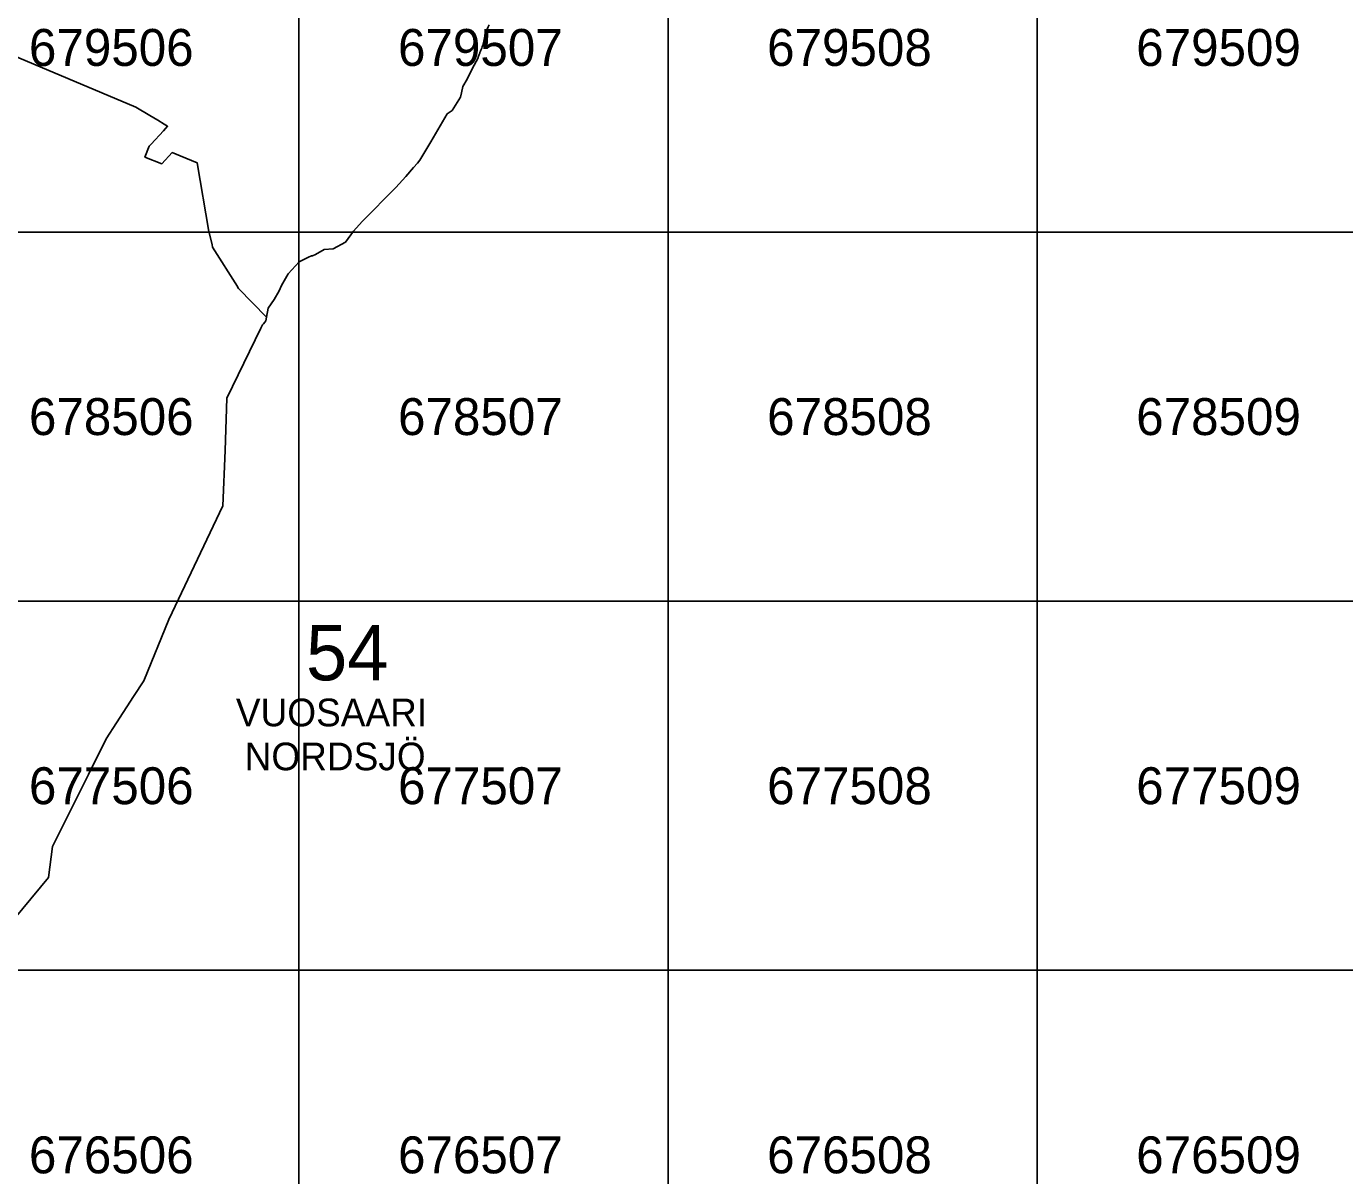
# Model space of a CAD drawing. Extents: x 25485000 to 25520000, y 6656775 to 6690000.
# Drawn here: x 25506262 to 25509833, y 6676444 to 6679557 of the extents above; entities that cross this region are included whole.
import ezdxf

# ---------------------------------------------------------------- set-up
doc = ezdxf.new("R2010")
doc.units = 0
doc.layers.add('Level 63', color=7, linetype='Continuous')

msp = doc.modelspace()

# ---------------------------------------------------------------- linework, layer by layer
at = {"layer": 'Level 63'}
for points in [[(25506000, 6679000), (25507000, 6679000), (25507000, 6680000), (25506000, 6680000)], [(25507000, 6679000), (25508000, 6679000), (25508000, 6680000), (25507000, 6680000)], [(25508000, 6679000), (25509000, 6679000), (25509000, 6680000), (25508000, 6680000)], [(25509000, 6679000), (25510000, 6679000), (25510000, 6680000), (25509000, 6680000)], [(25506000, 6678000), (25507000, 6678000), (25507000, 6679000), (25506000, 6679000)], [(25507000, 6678000), (25508000, 6678000), (25508000, 6679000), (25507000, 6679000)], [(25508000, 6678000), (25509000, 6678000), (25509000, 6679000), (25508000, 6679000)], [(25509000, 6678000), (25510000, 6678000), (25510000, 6679000), (25509000, 6679000)], [(25506000, 6677000), (25507000, 6677000), (25507000, 6678000), (25506000, 6678000)], [(25507000, 6677000), (25508000, 6677000), (25508000, 6678000), (25507000, 6678000)], [(25508000, 6677000), (25509000, 6677000), (25509000, 6678000), (25508000, 6678000)], [(25509000, 6677000), (25510000, 6677000), (25510000, 6678000), (25509000, 6678000)], [(25506000, 6676000), (25507000, 6676000), (25507000, 6677000), (25506000, 6677000)], [(25507000, 6676000), (25508000, 6676000), (25508000, 6677000), (25507000, 6677000)], [(25508000, 6676000), (25509000, 6676000), (25509000, 6677000), (25508000, 6677000)], [(25509000, 6676000), (25510000, 6676000), (25510000, 6677000), (25509000, 6677000)]]:
    msp.add_lwpolyline(points, close=True, dxfattribs=at)
for points in [[(25507515.5, 6679561.1), (25507513.1, 6679555.6), (25507508.1, 6679545.7), (25507506.4, 6679541.6), (25507505.4, 6679538.3), (25507503.5, 6679531), (25507500.8, 6679517.2), (25507498.2, 6679506.2), (25507496.6, 6679501.6), (25507495.2, 6679497.8), (25507492.9, 6679492.9), (25507491.6, 6679489.8), (25507490.3, 6679486.4), (25507489.8, 6679484.6), (25507488.5, 6679480.9), (25507486.9, 6679476), (25507484.7, 6679469.7), (25507470, 6679444.1), (25507455.8, 6679413.7), (25507443.7, 6679394.4), (25507440.3, 6679377.4), (25507437.6, 6679365), (25507415.1, 6679329), (25507401.8, 6679320), (25507357.5, 6679244.3), (25507327.2, 6679194.8), (25507321.6, 6679186.6), (25507310.2, 6679175), (25507289.3, 6679150.8), (25507262.5, 6679120.9), (25507171.6, 6679028.7), (25507147.8, 6679002.3), (25507126.6, 6678972.8), (25507092.5, 6678954.8), (25507068.5, 6678952.8), (25507045, 6678939.4), (25507036.5, 6678935.9), (25507034.3, 6678935.3), (25507025.8, 6678931.9), (25507000.8, 6678919.3), (25506971.1, 6678886.9), (25506953.1, 6678855.5), (25506946.7, 6678841), (25506932.5, 6678817.5), (25506916.2, 6678793.6), (25506912, 6678769.7), (25506836.4, 6678847.3), (25506834.8, 6678849.8), (25506833.5, 6678852.1), (25506766, 6678959.2), (25506764.6, 6678966.4), (25506755.9, 6679001.4), (25506724, 6679187.7), (25506677.9, 6679206.3), (25506656.1, 6679215.1), (25506628.2, 6679184.8), (25506582.7, 6679203.1), (25506594.6, 6679232.4), (25506599.5, 6679237.8), (25506633.2, 6679274.4), (25506644.2, 6679286.4), (25506634.8, 6679292.3), (25506617.4, 6679302.7), (25506595.6, 6679315.7), (25506558.1, 6679338.5), (25506096.7, 6679532.6)], [(25507515.5, 6679561.1), (25507513.1, 6679555.6), (25507508.1, 6679545.7), (25507506.4, 6679541.6), (25507505.4, 6679538.3), (25507503.5, 6679531), (25507500.8, 6679517.2), (25507498.2, 6679506.2), (25507496.6, 6679501.6), (25507495.2, 6679497.8), (25507492.9, 6679492.9), (25507491.6, 6679489.8), (25507490.3, 6679486.4), (25507489.8, 6679484.6), (25507488.5, 6679480.9), (25507486.9, 6679476), (25507484.7, 6679469.7), (25507470, 6679444.1), (25507455.8, 6679413.7), (25507443.7, 6679394.4), (25507440.3, 6679377.4), (25507437.6, 6679365), (25507415.1, 6679329), (25507401.8, 6679320), (25507357.5, 6679244.3), (25507327.2, 6679194.8), (25507321.6, 6679186.6), (25507310.2, 6679175), (25507289.3, 6679150.8), (25507262.5, 6679120.9), (25507171.6, 6679028.7), (25507147.8, 6679002.3), (25507126.6, 6678972.8), (25507092.5, 6678954.8), (25507068.5, 6678952.8), (25507045, 6678939.4), (25507036.5, 6678935.9), (25507034.3, 6678935.3), (25507025.8, 6678931.9), (25507000.8, 6678919.3), (25506971.1, 6678886.9), (25506953.1, 6678855.5), (25506946.7, 6678841), (25506932.5, 6678817.5), (25506916.2, 6678793.6), (25506910.1, 6678759.2), (25506908, 6678755.6), (25506903.8, 6678751.5), (25506901.5, 6678748.7), (25506897.1, 6678739.9), (25506804.8, 6678550), (25506799.9, 6678408.5), (25506794.2, 6678258.1), (25506647.7, 6677950.1), (25506579.8, 6677784.4), (25506551.7, 6677741.5), (25506505.8, 6677670.6), (25506477.7, 6677627.3), (25506429.7, 6677530.8), (25506332.4, 6677335.4), (25506321.3, 6677251.8), (25506203.7, 6677109.7)], [(25506203.7, 6677109.7), (25506321.3, 6677251.8), (25506332.4, 6677335.4), (25506429.7, 6677530.8), (25506477.7, 6677627.3), (25506505.8, 6677670.6), (25506551.7, 6677741.5), (25506579.8, 6677784.4), (25506647.7, 6677950.1), (25506794.2, 6678258.1), (25506799.9, 6678408.5), (25506804.8, 6678550), (25506897.1, 6678739.9), (25506901.5, 6678748.7), (25506903.8, 6678751.5), (25506908, 6678755.6), (25506910.1, 6678759.2), (25506912, 6678769.7), (25506836.4, 6678847.3), (25506834.8, 6678849.8), (25506833.5, 6678852.1), (25506766, 6678959.2), (25506764.6, 6678966.4), (25506755.9, 6679001.4), (25506724, 6679187.7), (25506677.9, 6679206.3), (25506656.1, 6679215.1), (25506628.2, 6679184.8), (25506582.7, 6679203.1), (25506594.6, 6679232.4), (25506599.5, 6679237.8), (25506633.2, 6679274.4), (25506644.2, 6679286.4), (25506634.8, 6679292.3), (25506617.4, 6679302.7), (25506595.6, 6679315.7), (25506558.1, 6679338.5), (25506096.7, 6679532.6)]]:
    msp.add_lwpolyline(points, dxfattribs=at)

# ---------------------------------------------------------------- texts
for s, height, p in [('679506', 100, (25506268.5, 6679450)), ('679507', 100, (25507268.5, 6679450)), ('679508', 100, (25508268.5, 6679450)), ('679509', 100, (25509268.5, 6679450)), ('678506', 100, (25506268.5, 6678450)), ('678507', 100, (25507268.5, 6678450)), ('678508', 100, (25508268.5, 6678450)), ('678509', 100, (25509268.5, 6678450)), ('54', 150, (25507019.2, 6677785.6)), ('VUOSAARI', 75, (25506829.1, 6677661)), ('NORDSJÖ', 75, (25506852.9, 6677541.9)), ('677506', 100, (25506268.5, 6677450)), ('677507', 100, (25507268.5, 6677450)), ('677508', 100, (25508268.5, 6677450)), ('677509', 100, (25509268.5, 6677450)), ('676506', 100, (25506268.5, 6676450)), ('676507', 100, (25507268.5, 6676450)), ('676508', 100, (25508268.5, 6676450)), ('676509', 100, (25509268.5, 6676450))]:
    msp.add_text(s, height=height, dxfattribs=at).set_placement(p)

doc.saveas('drawing.dxf')
